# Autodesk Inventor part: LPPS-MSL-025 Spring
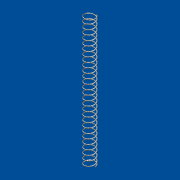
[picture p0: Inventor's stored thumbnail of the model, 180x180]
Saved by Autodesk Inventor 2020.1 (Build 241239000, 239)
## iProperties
Created: 2019-07
Part Number: LPPS-MSL-025 Spring
Material: Stainless Steel
Document SubType Name: Modeling
Designer: J. Nielson
Density: 8 g/cm^3
Appearance: Semi-Polished
Author: J. Nielson
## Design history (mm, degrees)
sketch "Sketch1"
  geometry: L1 (-2.5, 84.892)-(2.5, 84.892) reference; L2 (4, 36.246)-(-4, 36.246) reference; L3 (0, 36.246)-(0, 84.892); C1 r 0.152 at (1.905, 36.398); 1 further point
  constraints: 2 end point, 2 midpoint, 1 centre point, 1 tangent
  dimensions: "d0" = 48.6464 distance between parallel lines of L2 L1 (derived); "d1" = 0.3048 diameter of C1; "d2" = 1.905 distance from line of C1.centre L3
coil "Coil1" sketch "Sketch1" pitch "d3" = 25.4; turns "d5" = 27; dims "d4" = 48.3416 (= d0 - d1), "d6" = 0, angle "d7" = 30 deg, angle "d8" = 180 deg, "d9" = 30 deg, "d10" = 180 deg
body "Solid1"
node "Reference1"
node "Reference2"
